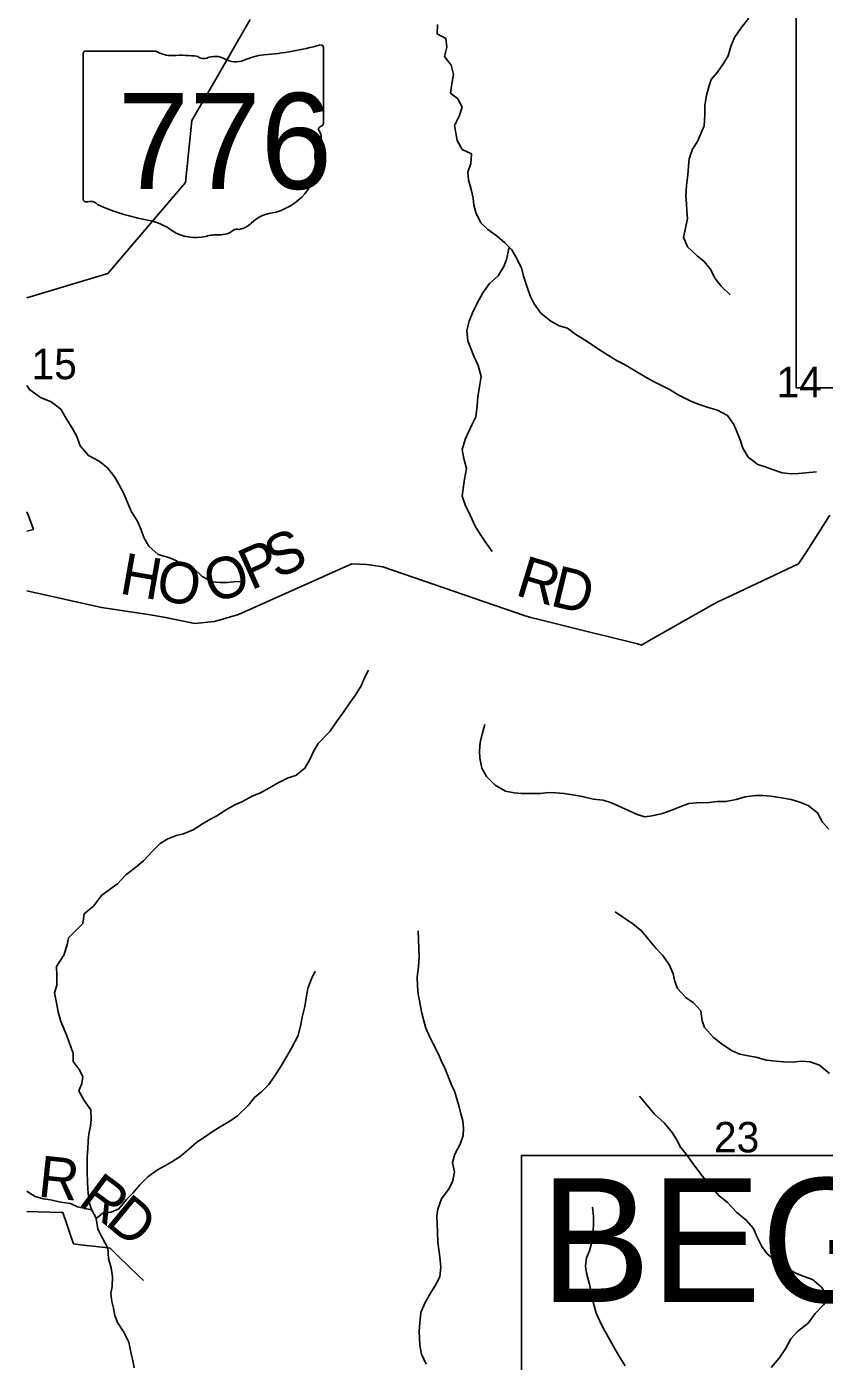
# Model space of a CAD drawing. Extents: x 0 to 34, y 0 to 22.
# Drawn here: x 2.1 to 3.195, y 16.276 to 18.109 of the extents above; entities that cross this region are included whole.
import ezdxf

# ---------------------------------------------------------------- set-up
doc = ezdxf.new("R2010")
doc.units = 0
for name, color, linetype in [('GM_X_Minor_Lake', 7, 'Continuous'), ('GM_X_Minor_River', 7, 'Continuous'), ('GM_X_Section_Text', 7, 'Continuous'), ('GM_X_State_Location', 7, 'Continuous'), ('GM_X_State_Route', 7, 'Continuous'), ('GM_X_State_Shield', 7, 'Continuous'), ('GM_X_Township_Road', 7, 'Continuous'), ('GM_X_Township_Road_Text', 7, 'Continuous'), ('SH_Text', 7, 'Continuous')]:
    doc.layers.add(name, color=color, linetype=linetype)

msp = doc.modelspace()

# ---------------------------------------------------------------- linework, layer by layer
at = {"layer": 'GM_X_Minor_Lake'}
msp.add_line((2.1, 17.4159), (2.1094, 17.4181), dxfattribs=at)
msp.add_lwpolyline([(2.1094, 17.4181), (2.1019, 17.4383), (2.1, 17.4423)], dxfattribs=at)
at = {"layer": 'GM_X_Minor_River'}
for points in [[(3.1456, 18.2471), (3.1339, 18.2375), (3.1342, 18.2269), (3.1364, 18.2155), (3.1386, 18.2026), (3.1378, 18.1897), (3.1332, 18.1783), (3.1213, 18.1636), (3.1148, 18.1534), (3.1034, 18.1391), (3.0957, 18.1289), (3.0896, 18.1183), (3.0808, 18.107), (3.072, 18.0938), (3.067, 18.0813), (3.0632, 18.0688), (3.0567, 18.0582), (3.0483, 18.0461), (3.0399, 18.036), (3.0368, 18.0261), (3.0333, 18.0144), (3.0313, 18.0011), (3.0312, 17.9878), (3.0304, 17.9724)], [(2.6639, 18.1117), (2.6634, 18.0988), (2.6755, 18.0926), (2.6769, 18.0805), (2.6738, 18.0676), (2.6828, 18.0558), (2.6861, 18.0432), (2.6837, 18.03), (2.6821, 18.0175), (2.6919, 18.0094), (2.6979, 17.998), (2.694, 17.9859), (2.6876, 17.9731)], [(2.6876, 17.9731), (2.691, 17.9523), (2.6981, 17.9401), (2.7109, 17.934), (2.7098, 17.9208), (2.7056, 17.909), (2.7067, 17.8984), (2.7104, 17.8851), (2.713, 17.8734), (2.7141, 17.8635), (2.7167, 17.8536), (2.7235, 17.8392), (2.7333, 17.8304), (2.7461, 17.8209), (2.7563, 17.8118), (2.7661, 17.8023), (2.7717, 17.7928), (2.7792, 17.7776), (2.7822, 17.7662), (2.7867, 17.7522), (2.7912, 17.7393), (2.7968, 17.7282), (2.8058, 17.7153), (2.8198, 17.7043), (2.8311, 17.6978), (2.8425, 17.6947), (2.8542, 17.6859), (2.8681, 17.6772), (2.8851, 17.6657), (2.8987, 17.6573), (2.9108, 17.6497), (2.9206, 17.6448), (2.9323, 17.6379), (2.9515, 17.6264), (2.9625, 17.6207), (2.9727, 17.6154), (2.9825, 17.6104), (2.9953, 17.6028), (3.0112, 17.5948), (3.0218, 17.5905), (3.0358, 17.5859), (3.0486, 17.5821), (3.0622, 17.5748), (3.0708, 17.5623), (3.0757, 17.5513), (3.0798, 17.5414), (3.0832, 17.53), (3.0904, 17.5175), (3.1039, 17.5076), (3.1141, 17.5041), (3.124, 17.5007), (3.1372, 17.4961), (3.1497, 17.4945), (3.1595, 17.4953), (3.1845, 17.4974)], [(3.0304, 17.9724), (3.0212, 17.951), (3.0144, 17.9404), (3.0098, 17.9272), (3.0086, 17.917), (3.0078, 17.9052), (3.0059, 17.8908), (3.005, 17.8764), (3.0058, 17.8658), (3.0065, 17.8559), (3.0072, 17.8453), (3.0045, 17.8321), (3.0018, 17.8196), (3.0074, 17.8063), (3.0206, 17.7941), (3.0304, 17.7861), (3.0383, 17.7762), (3.0451, 17.7629), (3.0534, 17.7523), (3.0658, 17.7405)], [(2.7626, 17.8057), (2.7588, 17.789), (2.755, 17.7792), (2.7474, 17.7667), (2.7353, 17.7558), (2.7265, 17.7433), (2.7185, 17.7289), (2.712, 17.7157), (2.7074, 17.7043), (2.7044, 17.6914), (2.7058, 17.6774), (2.7096, 17.6668), (2.7141, 17.6561), (2.7197, 17.6432), (2.7242, 17.6281), (2.7219, 17.6144), (2.7195, 17.6004), (2.7187, 17.5879), (2.7168, 17.5727), (2.7111, 17.5618), (2.7065, 17.5519), (2.7019, 17.5417), (2.6977, 17.5281), (2.7003, 17.5156), (2.7037, 17.5019), (2.7013, 17.4871), (2.6998, 17.4777), (2.6979, 17.464), (2.702, 17.4519), (2.7087, 17.4378), (2.7159, 17.423), (2.7215, 17.4131), (2.7298, 17.4006), (2.7392, 17.3881)], [(2.1, 17.6159), (2.1037, 17.6103), (2.1188, 17.5997), (2.1335, 17.5936), (2.1467, 17.5836), (2.1543, 17.5707), (2.1618, 17.5582), (2.1689, 17.546), (2.1734, 17.5331), (2.1847, 17.5198), (2.1994, 17.5122), (2.2111, 17.5027), (2.2209, 17.4901), (2.2273, 17.4787), (2.2333, 17.4677), (2.2386, 17.4552), (2.2438, 17.4426), (2.2521, 17.4297), (2.257, 17.4176), (2.2607, 17.4073), (2.2675, 17.3955), (2.2807, 17.3837), (2.295, 17.3799), (2.3049, 17.3757), (2.3184, 17.3669), (2.329, 17.365), (2.3411, 17.3536), (2.3547, 17.3463), (2.3653, 17.3455), (2.3755, 17.3455), (2.3887, 17.3466), (2.3986, 17.3465)], [(2.1955, 16.4723), (2.1888, 16.4846), (2.1858, 16.4941), (2.184, 16.5119), (2.1833, 16.5229), (2.183, 16.5339), (2.183, 16.5574), (2.1838, 16.5676), (2.1843, 16.5786), (2.1854, 16.5884), (2.1874, 16.5987), (2.1885, 16.6085), (2.1882, 16.6214), (2.1788, 16.634), (2.1716, 16.6473), (2.1758, 16.6575), (2.177, 16.6669), (2.1721, 16.6768), (2.1639, 16.6878), (2.1639, 16.6985), (2.1605, 16.7079), (2.1549, 16.7228), (2.1508, 16.733), (2.1467, 16.7425), (2.1433, 16.7558), (2.1407, 16.7683), (2.1381, 16.7819), (2.1415, 16.7918), (2.1416, 16.8054), (2.1409, 16.8179), (2.1511, 16.8335), (2.1557, 16.8478), (2.1573, 16.8573), (2.1668, 16.8671), (2.177, 16.8773), (2.179, 16.8906), (2.1915, 16.9008), (2.2029, 16.9155), (2.215, 16.9249), (2.2245, 16.9317), (2.2363, 16.9438), (2.2477, 16.9529), (2.2606, 16.9631), (2.2727, 16.9767), (2.2834, 16.9868), (2.294, 16.9933), (2.3053, 16.9978), (2.3152, 17.0004), (2.3285, 17.006), (2.3413, 17.0139), (2.3516, 17.0199), (2.3618, 17.0256), (2.3721, 17.0324), (2.3857, 17.0399), (2.3956, 17.0444), (2.4103, 17.0523), (2.4209, 17.0564), (2.4323, 17.0628), (2.4452, 17.0704), (2.4592, 17.0772), (2.4695, 17.0805), (2.482, 17.0903), (2.4888, 17.1024), (2.4934, 17.1123), (2.5003, 17.1244), (2.5162, 17.141), (2.5261, 17.1554), (2.5352, 17.1675), (2.5436, 17.1803), (2.5508, 17.1901), (2.5592, 17.2034), (2.5638, 17.2144), (2.5691, 17.2249)], [(3.0371, 17.0431), (3.0205, 17.0428), (3.0092, 17.0421), (2.9982, 17.038), (2.9868, 17.0334), (2.9728, 17.0282), (2.9588, 17.0248), (2.9486, 17.0237), (2.938, 17.0268), (2.9255, 17.0329), (2.913, 17.0383), (2.9029, 17.0429), (2.8915, 17.0467), (2.8779, 17.0479), (2.8628, 17.0517), (2.8522, 17.0533), (2.8382, 17.0556), (2.8261, 17.0564), (2.8163, 17.0572), (2.8057, 17.0557), (2.7928, 17.0558), (2.7792, 17.0558), (2.7694, 17.0566), (2.7576, 17.059), (2.7433, 17.0673), (2.7312, 17.0791), (2.7249, 17.0905), (2.7223, 17.1042), (2.7219, 17.1141), (2.7227, 17.1258), (2.7254, 17.1372), (2.7292, 17.1504)], [(3.2016, 17.0069), (3.1925, 17.0164), (3.1858, 17.0293), (3.1729, 17.0392), (3.1616, 17.0438), (3.1495, 17.0476), (3.1363, 17.0499), (3.1219, 17.0519), (3.1113, 17.0531), (3.1011, 17.0531), (3.0867, 17.0509), (3.0742, 17.0475), (3.0599, 17.0449), (3.0481, 17.0446), (3.0371, 17.0431)], [(3.2022, 16.671), (3.1886, 16.6824), (3.1758, 16.687), (3.1641, 16.6882), (3.1508, 16.6867), (3.1387, 16.6872), (3.1289, 16.688), (3.116, 16.6895), (3.1013, 16.6934), (3.0907, 16.6953), (3.079, 16.6976), (3.0688, 16.7022), (3.0552, 16.711), (3.0431, 16.7205), (3.0307, 16.7342), (3.0273, 16.7437), (3.0255, 16.757), (3.0157, 16.768), (3.0051, 16.7756), (2.9938, 16.7878), (2.9901, 16.7973), (2.9875, 16.8079), (2.9822, 16.8208), (2.9732, 16.8337), (2.9638, 16.8432), (2.9525, 16.8569), (2.9446, 16.8668), (2.9321, 16.8767), (2.9182, 16.8863), (2.908, 16.8931)], [(2.6484, 16.2721), (2.6421, 16.2857), (2.6398, 16.2979), (2.6395, 16.3077), (2.6391, 16.3172), (2.6399, 16.3289), (2.6411, 16.343), (2.6469, 16.3566), (2.6545, 16.3695), (2.6617, 16.3812), (2.6674, 16.3918), (2.6686, 16.405), (2.6671, 16.4194), (2.6657, 16.4297), (2.6646, 16.4392), (2.6639, 16.4539), (2.6635, 16.4649), (2.6632, 16.4752), (2.6647, 16.485), (2.6697, 16.499), (2.68, 16.5134), (2.6853, 16.5236), (2.6872, 16.5361), (2.6846, 16.549), (2.6877, 16.5604), (2.6953, 16.574), (2.6992, 16.5861), (2.6996, 16.5956), (2.6988, 16.6062), (2.6962, 16.6157), (2.694, 16.6255), (2.6906, 16.6366), (2.6873, 16.6468), (2.6828, 16.6567), (2.6786, 16.6669), (2.6741, 16.6783), (2.6693, 16.6889), (2.6651, 16.6988), (2.658, 16.7117), (2.6535, 16.7212), (2.6482, 16.7334), (2.6453, 16.7436), (2.6419, 16.7558), (2.6397, 16.7687), (2.6374, 16.78), (2.6364, 16.7907), (2.636, 16.8039), (2.638, 16.8179), (2.6388, 16.8316), (2.6384, 16.843), (2.6381, 16.8551), (2.6374, 16.8672)], [(2.4784, 16.7484), (2.4819, 16.7632), (2.4842, 16.7776), (2.4862, 16.7878), (2.4911, 16.8011), (2.4961, 16.8117)], [(2.2474, 16.2668), (2.2456, 16.2766), (2.2426, 16.2907), (2.2404, 16.302), (2.2336, 16.3161), (2.2249, 16.3294), (2.2212, 16.3389), (2.219, 16.3487), (2.2171, 16.3582), (2.2156, 16.3689), (2.2172, 16.3787), (2.218, 16.392), (2.2158, 16.4045), (2.2124, 16.417), (2.2113, 16.4314), (2.2042, 16.4451), (2.1978, 16.4572), (2.1952, 16.472), (2.2047, 16.4796), (2.216, 16.4807), (2.2263, 16.4852), (2.2369, 16.498), (2.2464, 16.5075), (2.2552, 16.5181), (2.2665, 16.5294), (2.2794, 16.5388), (2.2897, 16.5445), (2.2992, 16.5497), (2.3109, 16.5573), (2.3223, 16.5667), (2.3337, 16.5769), (2.3454, 16.5848), (2.3561, 16.592), (2.3655, 16.598), (2.3788, 16.6055), (2.3894, 16.6131), (2.4039, 16.627), (2.413, 16.638), (2.4225, 16.6459), (2.4319, 16.6557), (2.4407, 16.6678), (2.4494, 16.6818), (2.4567, 16.6939), (2.4639, 16.7068), (2.4727, 16.7234), (2.4765, 16.7386), (2.4784, 16.7484)], [(3.2013, 16.3626), (3.1913, 16.3777), (3.1789, 16.3883), (3.166, 16.3929), (3.1562, 16.3971), (3.1434, 16.404), (3.1301, 16.4124), (3.1169, 16.4234), (3.1094, 16.4337), (3.103, 16.4466), (3.0978, 16.4584), (3.088, 16.4698), (3.0752, 16.4804), (3.0624, 16.4938), (3.0503, 16.5037), (3.0394, 16.5166), (3.0273, 16.5307), (3.016, 16.5459), (3.0059, 16.5599), (2.9979, 16.5702), (2.9923, 16.5804), (2.9863, 16.5903), (2.9754, 16.6036), (2.9622, 16.6151), (2.9415, 16.6401)], [(2.1891, 16.484), (2.1699, 16.4881), (2.1601, 16.4926), (2.1469, 16.4946), (2.1325, 16.4977), (2.1227, 16.4992), (2.1117, 16.5023), (2.1019, 16.508), (2.1, 16.5096)], [(2.9219, 16.2699), (2.9125, 16.2843), (2.9069, 16.2942), (2.8982, 16.3094), (2.8896, 16.325), (2.8821, 16.3421), (2.8776, 16.3572), (2.8754, 16.3679), (2.8728, 16.3819), (2.8687, 16.3971), (2.8672, 16.4065), (2.8688, 16.4179), (2.8726, 16.4278), (2.8753, 16.4384), (2.8768, 16.4486), (2.8784, 16.4619), (2.8781, 16.4747), (2.877, 16.4876)], [(3.1224, 16.2676), (3.1331, 16.2801), (3.1418, 16.2929), (3.1494, 16.3066), (3.1582, 16.3171), (3.173, 16.3281), (3.1825, 16.3417), (3.1942, 16.3534), (3.2045, 16.3666)]]:
    msp.add_lwpolyline(points, dxfattribs=at)
at = {"layer": 'GM_X_State_Route'}
msp.add_lwpolyline([(2.1, 17.7362), (2.2115, 17.7696), (2.3179, 17.8946), (2.3268, 17.9799), (2.3595, 18.0365), (2.4069, 18.1187)], dxfattribs=at)
at = {"layer": 'GM_X_State_Shield'}
for p, q in [((2.1777, 18.0719), (2.1777, 17.8718)), ((2.2775, 18.0753), (2.181, 18.0753)), ((2.5073, 17.9756), (2.5073, 18.0803)), ((2.5073, 17.9756), (2.5073, 17.9756))]:
    msp.add_line(p, q, dxfattribs=at)
for centre, major_axis, start_param, end_param in [((2.1815, 18.0723), (0.00382, 0), 1.712693, 3.28349), ((2.3005, 18.0985), (0.037, 0), 4.042523, 4.731795), ((2.3899, 18.3481), (0.3495, 0), 4.814394, 5.042369), ((2.5037, 18.0807), (0.00367, 0), 6.141152, 7.989035), ((2.3128, 17.963), (0.133, 0), 1.404758, 1.657858), ((2.343, 18.0733), (0.0107, 0), 3.836095, 5.185415), ((2.3586, 18.0502), (0.0222, 0), 0.950623, 2.079405), ((2.3873, 18.0819), (0.0267, 0), 4.081561, 5.145723), ((2.4345, 18.0142), (0.0703, 0), 1.699011, 2.107814), ((2.5065, 17.9679), (0.00568, 0), 1.883978, 3.671073), ((2.4704, 17.9547), (0.0341, 0), 5.934695, 6.695948), ((2.5034, 17.9752), (0.00393, 0), 5.05454, 6.418171), ((2.5205, 17.9318), (0.0248, 0), 2.387724, 3.262537), ((2.4095, 17.9185), (0.0874, 0), 5.101752, 6.440018), ((2.1815, 17.8713), (0.00385, 0), 3.00124, 4.508301), ((2.1821, 17.8918), (0.0294, 0), 4.665946, 4.897461), ((2.1881, 17.8602), (0.0106, 0), 0.519207, 1.627899), ((2.322, 18.04), (0.2524, 0), 4.195997, 4.488961), ((2.4464, 17.8156), (0.0479, 0), 1.647645, 2.488434), ((2.2467, 17.7818), (0.079, 0), 0.823519, 1.323587), ((2.3857, 17.8524), (0.0282, 0), 4.937069, 5.64225), ((2.3321, 17.8592), (0.0501, 0), 4.026481, 4.996735), ((2.3611, 17.79), (0.0412, 0), 1.495662, 1.94098), ((2.3648, 17.8442), (0.0267, 0), 4.691044, 5.507374), ((2.3889, 17.8248), (0.00752, 0), 1.147584, 2.315152)]:
    msp.add_ellipse(centre, major_axis=major_axis, ratio=0.8, start_param=start_param, end_param=end_param, dxfattribs=at)
at = {"layer": 'GM_X_Township_Road'}
for points in [[(2.8942, 17.272), (2.9386, 17.261), (2.9441, 17.2596), (2.9565, 17.2666), (3.043, 17.3156), (3.0481, 17.3185), (3.0608, 17.3245), (3.1597, 17.3711), (3.1706, 17.3877), (3.2028, 17.4379)], [(2.1, 17.3341), (2.2027, 17.3111), (2.2667, 17.3014), (2.2883, 17.2976), (2.3309, 17.2891), (2.3579, 17.292), (2.3906, 17.3017), (2.5465, 17.371), (2.5668, 17.37), (2.5889, 17.3671), (2.7842, 17.2995), (2.792, 17.2972), (2.8035, 17.2944), (2.8807, 17.2753), (2.8942, 17.272)], [(2.1, 16.4815), (2.1473, 16.4803), (2.1498, 16.4802), (2.1551, 16.4644), (2.1612, 16.4463), (2.1642, 16.4373), (2.1737, 16.4361), (2.2117, 16.4316), (2.2147, 16.4312), (2.2262, 16.42), (2.2537, 16.3934), (2.2606, 16.3868)]]:
    msp.add_lwpolyline(points, dxfattribs=at)
at = {"layer": 'SH_Text'}
for points in [[(3.1565, 18.3776), (4.9408, 18.3776), (4.9408, 17.6129), (3.1565, 17.6129)], [(2.7795, 16.5585), (4.7911, 16.5585), (4.7911, 15.8085), (2.7795, 15.8085)]]:
    msp.add_lwpolyline(points, close=True, dxfattribs=at)

# ---------------------------------------------------------------- texts
at = {"layer": 'GM_X_Section_Text'}
for s, p in [('15', (2.1066, 17.6246)), ('14', (3.1295, 17.5998)), ('23', (3.0436, 16.5628))]:
    msp.add_text(s, height=0.04186, rotation=0, dxfattribs=at).set_placement(p)
at = {"layer": 'GM_X_State_Location'}
msp.add_text('776', height=0.000189, rotation=0, dxfattribs=at).set_placement((2.272, 17.9447))
for s in ['s', 'r']:
    msp.add_text(s, height=0.000189, dxfattribs=at).set_placement((2.3388, 17.9585))
at = {"layer": 'GM_X_State_Shield'}
msp.add_text('776', height=0.13184, dxfattribs=at).set_placement((2.2252, 17.8859))
at = {"layer": 'GM_X_Township_Road_Text'}
for s, rotation, p in [('S', 23.9654, (2.4429, 17.3498)), ('P', 24.1545, (2.408, 17.3341)), ('H', 350.0454, (2.2258, 17.3306)), ('O', 350.7057, (2.2758, 17.3219)), ('O', 18.3366, (2.3547, 17.3161)), ('R', 343.0129, (2.7691, 17.3287)), ('D', 346.3599, (2.8172, 17.3141)), ('R', 353.8684, (2.1142, 16.5023)), ('R', 323.4759, (2.1689, 16.4921)), ('D', 320.4458, (2.2057, 16.4649))]:
    msp.add_text(s, height=0.0568, rotation=rotation, dxfattribs=at).set_placement(p)
at = {"layer": 'SH_Text'}
msp.add_text('BEGIN PROJECT', height=0.17, dxfattribs=at).set_placement((2.8051, 16.3574))

doc.saveas('drawing.dxf')
